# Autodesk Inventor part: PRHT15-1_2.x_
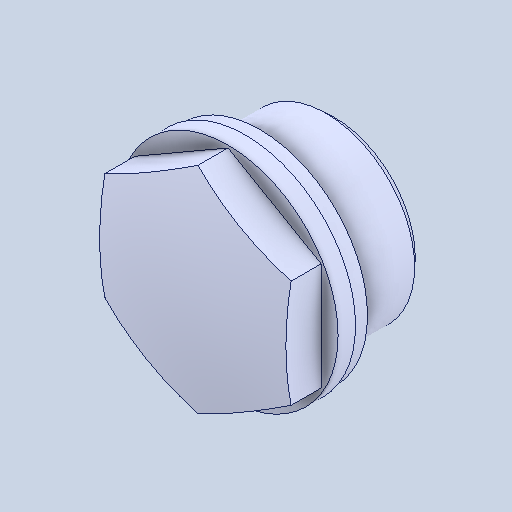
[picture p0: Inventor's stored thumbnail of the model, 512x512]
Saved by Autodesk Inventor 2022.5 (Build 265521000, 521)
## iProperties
Created: 2024-05
Part Number: PRHT15-1_2.x_
Material: 一般
Document SubType Name: Modeling
Designer: ImaoCorp
Density: 1 g/cm^3
Appearance: 既定
Author: ImaoCorp
Sending System: SOLIDWORKS 2022-2022290
MC: AMD64
MC_MODEL: Intel64 Family 6 Model 60 Stepping 3, GenuineIntel
OS: Windows_NT
FRU: Parasolid Version 33.1, build 260,  4-25-2022
FORMAT: text
GUISE: transmit
KEY: FILEPRHT15-1_2.x_t
DATE: Mon May 20 16:41:24 2024
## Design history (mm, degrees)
feature "Base1"
node "ソリッド1"
